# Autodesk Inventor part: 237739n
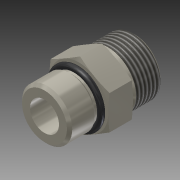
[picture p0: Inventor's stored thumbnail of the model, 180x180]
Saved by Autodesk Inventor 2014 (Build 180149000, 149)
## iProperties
Company: Autodesk, Inc.
Shininess: 64.0
Length Units: 11272
Angle Units: 11279
Time Units: 11290
Mass Units: 11286
Length Display Precision: 3
Angle Display Precision: 2
Compacted: True
Part Number: 237739n
Document SubType Name: Modeling
Created: 2003-10
Designer: Autodesk, Inc.
Manufacturer: Standard
Standards Organization: Custom
Density: 3.18 g/cm^3
Material: Silicon Nitride
Mass: 78.3716 g
Surface Area: 96.6935 cm^2
Volume: 24.6452 cm^3
Appearance: Si Nitride (Polished)
Density: 0.0
Volumn: 0.0
Area: 0.0
PropertySet Name: Model Information
Control State: 0
Master: False
Checked Out: False
Author: Autodesk, Inc.
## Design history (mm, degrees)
feature "Base1"
sketch "Sketch1"
  geometry: L1 (0, 12.631)-(0, 16.934) reference; C1 r 1.537 at (13.551, 14.783); A1 r 1.524 centre (13.551, 14.783) between (13.551, 13.259) and (13.551, 16.307) reference
  constraints: 1 centre point, 1 coincident
  dimensions: "d0" = 3.0734 diameter of C1
revolve "Revolution1" sketch "Sketch1" stored, may be unused: angle "d1" = 90 deg
thread "Thread1" dims "d2" = 25.4, "d3" = 0
body "Solid1"
